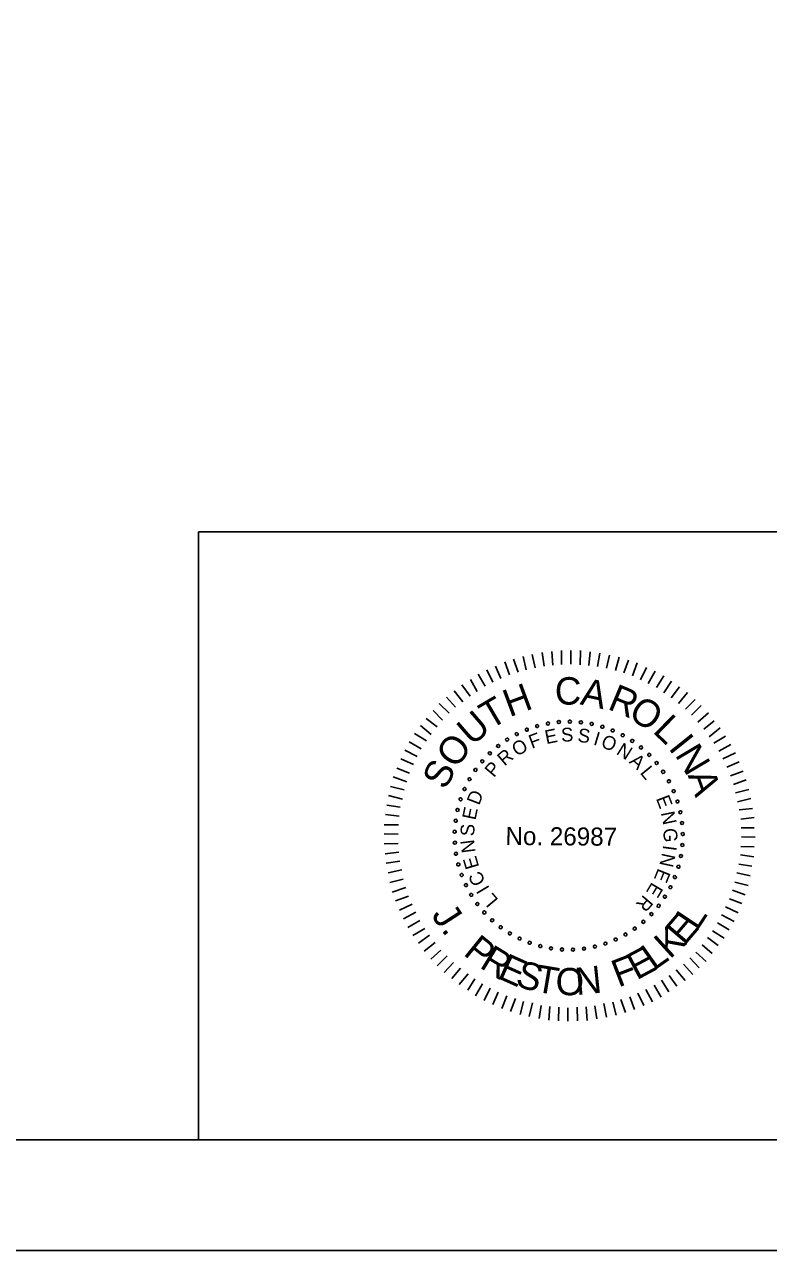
# Model space of a CAD drawing. Extents: x 96 to 240, y 601 to 689.
# Drawn here: x 183.23 to 196.68, y 601 to 623.18 of the extents above; entities that cross this region are included whole.
import ezdxf

# ---------------------------------------------------------------- set-up
doc = ezdxf.new("R2010")
doc.units = 0
for name, color, linetype in [('BR_BORDER LINES', 7, 'Continuous'), ('BR_TEXT', 7, 'Continuous'), ('Level 31', 7, 'Continuous')]:
    doc.layers.add(name, color=color, linetype=linetype)

msp = doc.modelspace()

# ---------------------------------------------------------------- linework, layer by layer
at = {"layer": 'BR_BORDER LINES'}
for p, q in [((186.375, 614.004), (207.836, 614.004)), ((186.375, 603.004), (186.375, 614.004)), ((103.173, 603.003), (237.837, 603.003))]:
    msp.add_line(p, q, dxfattribs=at)
at = {"layer": 'BR_TEXT'}
for p, q in [((192.938, 611.601), (192.94, 611.858)), ((193.106, 611.61), (193.108, 611.857)), ((193.274, 611.598), (193.283, 611.856)), ((191.996, 611.416), (191.912, 611.651)), ((192.154, 611.467), (192.067, 611.697)), ((192.299, 611.507), (192.246, 611.751)), ((192.464, 611.546), (192.407, 611.784)), ((192.622, 611.576), (192.586, 611.82)), ((192.78, 611.592), (192.765, 611.836)), ((193.435, 611.587), (193.455, 611.83)), ((193.59, 611.568), (193.633, 611.811)), ((193.751, 611.536), (193.808, 611.772)), ((193.915, 611.493), (193.979, 611.736)), ((194.063, 611.451), (194.15, 611.68)), ((194.22, 611.398), (194.308, 611.631)), ((191.555, 611.211), (191.433, 611.428)), ((191.693, 611.282), (191.588, 611.506)), ((191.841, 611.349), (191.747, 611.573)), ((194.364, 611.328), (194.475, 611.55)), ((194.507, 611.258), (194.633, 611.481)), ((194.658, 611.185), (194.787, 611.4)), ((191.289, 611.031), (191.133, 611.235)), ((191.413, 611.116), (191.292, 611.333)), ((194.791, 611.088), (194.927, 611.303)), ((194.924, 611.001), (195.07, 611.202)), ((191.023, 610.831), (190.856, 611.01)), ((191.154, 610.929), (190.995, 611.13)), ((195.054, 610.897), (195.216, 611.095)), ((195.18, 610.796), (195.353, 610.973)), ((190.788, 610.599), (190.614, 610.769)), ((190.905, 610.722), (190.728, 610.898)), ((195.292, 610.686), (195.465, 610.859)), ((190.687, 610.473), (190.489, 610.629)), ((195.404, 610.561), (195.595, 610.728)), ((195.513, 610.433), (195.7, 610.586)), ((190.496, 610.224), (190.281, 610.356)), ((190.583, 610.34), (190.385, 610.5)), ((195.608, 610.298), (195.805, 610.455)), ((195.696, 610.181), (195.907, 610.31)), ((190.399, 610.077), (190.184, 610.206)), ((195.784, 610.033), (195.998, 610.158)), ((190.259, 609.793), (190.03, 609.895)), ((190.329, 609.94), (190.103, 610.052)), ((195.855, 609.895), (196.086, 610.003)), ((190.189, 609.639), (189.957, 609.727)), ((195.926, 609.747), (196.154, 609.844)), ((195.994, 609.592), (196.221, 609.675)), ((190.14, 609.479), (189.894, 609.57)), ((196.047, 609.43), (196.278, 609.517)), ((190.062, 609.167), (189.812, 609.231)), ((190.091, 609.335), (189.847, 609.395)), ((196.087, 609.285), (196.328, 609.342)), ((190.019, 609.023), (189.776, 609.056)), ((196.12, 609.117), (196.361, 609.177)), ((196.153, 608.972), (196.39, 609.001)), ((190.001, 608.858), (189.754, 608.888)), ((196.179, 608.807), (196.423, 608.833)), ((189.981, 608.536), (189.73, 608.538)), ((189.989, 608.701), (189.732, 608.703)), ((196.185, 608.649), (196.425, 608.647)), ((189.986, 608.364), (189.729, 608.359)), ((196.182, 608.313), (196.422, 608.304)), ((196.194, 608.485), (196.438, 608.483)), ((189.996, 608.21), (189.748, 608.181)), ((196.174, 608.159), (196.418, 608.126)), ((190.011, 608.045), (189.767, 608.009)), ((190.051, 607.887), (189.8, 607.834)), ((196.145, 607.994), (196.382, 607.954)), ((190.077, 607.718), (189.833, 607.662)), ((196.074, 607.669), (196.314, 607.608)), ((196.11, 607.837), (196.349, 607.78)), ((190.124, 607.57), (189.876, 607.486)), ((190.171, 607.415), (189.937, 607.331)), ((196.031, 607.521), (196.261, 607.434)), ((190.238, 607.267), (190.007, 607.159)), ((195.905, 607.22), (196.131, 607.109)), ((195.975, 607.367), (196.201, 607.28)), ((190.306, 607.122), (190.078, 607.004)), ((190.373, 606.974), (190.156, 606.849)), ((195.832, 607.077), (196.061, 606.955)), ((190.468, 606.826), (190.251, 606.701)), ((195.668, 606.783), (195.877, 606.654)), ((195.759, 606.93), (195.971, 606.801)), ((190.553, 606.708), (190.353, 606.562)), ((190.655, 606.574), (190.454, 606.417)), ((195.481, 606.534), (195.665, 606.374)), ((195.578, 606.667), (195.773, 606.518)), ((190.753, 606.439), (190.577, 606.276)), ((190.869, 606.335), (190.689, 606.155)), ((195.256, 606.299), (195.426, 606.115)), ((195.37, 606.401), (195.557, 606.234)), ((190.985, 606.214), (190.815, 606.03)), ((191.114, 606.11), (190.952, 605.922)), ((195.014, 606.078), (195.173, 605.888)), ((195.142, 606.18), (195.312, 605.993)), ((191.248, 606.006), (191.088, 605.815)), ((191.37, 605.919), (191.245, 605.711)), ((194.748, 605.891), (194.88, 605.681)), ((194.883, 605.976), (195.025, 605.782)), ((191.51, 605.829), (191.385, 605.613)), ((191.647, 605.749), (191.539, 605.526)), ((191.794, 605.679), (191.696, 605.456)), ((194.317, 605.658), (194.425, 605.434)), ((194.462, 605.725), (194.583, 605.501)), ((194.613, 605.803), (194.739, 605.586)), ((191.948, 605.609), (191.86, 605.383)), ((192.105, 605.559), (192.014, 605.327)), ((192.249, 605.51), (192.192, 605.274)), ((192.414, 605.481), (192.353, 605.235)), ((192.571, 605.435), (192.532, 605.202)), ((192.729, 605.417), (192.71, 605.17)), ((193.384, 605.412), (193.4, 605.164)), ((193.539, 605.427), (193.578, 605.194)), ((193.701, 605.471), (193.754, 605.223)), ((193.866, 605.497), (193.926, 605.259)), ((194.014, 605.544), (194.098, 605.309)), ((194.172, 605.59), (194.256, 605.363)), ((192.887, 605.405), (192.885, 605.158)), ((193.055, 605.394), (193.053, 605.15)), ((193.223, 605.403), (193.228, 605.155))]:
    msp.add_line(p, q, dxfattribs=at)
for centre, start, end in [((192.498, 610.49), 16.1422, 196.1422), ((192.692, 610.536), 10.6038, 190.6038), ((192.692, 610.536), 190.6038, 10.6038), ((192.89, 610.563), 5.0653, 185.0653), ((192.89, 610.563), 185.0653, 5.0653), ((193.089, 610.57), 359.5268, 179.5268), ((193.089, 610.57), 179.5268, 359.5268), ((193.288, 610.558), 353.9884, 173.9884), ((193.288, 610.558), 173.9884, 353.9884), ((193.485, 610.528), 348.4499, 168.4499), ((193.485, 610.528), 168.4499, 348.4499), ((192.128, 610.344), 27.2191, 207.2191), ((192.128, 610.344), 207.2191, 27.2191), ((192.31, 610.426), 21.6807, 201.6807), ((192.31, 610.426), 201.6807, 21.6807), ((192.498, 610.49), 196.1422, 16.1422), ((193.678, 610.478), 162.9114, 342.9114), ((193.678, 610.478), 342.9114, 162.9114), ((193.865, 610.41), 157.373, 337.373), ((193.865, 610.41), 337.373, 157.373), ((194.045, 610.324), 151.8345, 331.8345), ((194.045, 610.324), 331.8345, 151.8345), ((191.793, 610.129), 38.2961, 218.2961), ((191.793, 610.129), 218.2961, 38.2961), ((191.955, 610.244), 32.7576, 212.7576), ((191.955, 610.244), 212.7576, 32.7576), ((194.216, 610.221), 146.2961, 326.2961), ((194.216, 610.221), 326.2961, 146.2961), ((194.376, 610.102), 140.7576, 320.7576), ((194.376, 610.102), 320.7576, 140.7576), ((191.505, 609.854), 49.373, 229.373), ((191.505, 609.854), 229.373, 49.373), ((191.642, 609.998), 43.8345, 223.8345), ((191.642, 609.998), 223.8345, 43.8345), ((194.524, 609.969), 135.2191, 315.2191), ((194.524, 609.969), 315.2191, 135.2191), ((194.658, 609.821), 309.6807, 129.6807), ((191.382, 609.697), 54.9114, 234.9114), ((191.382, 609.697), 234.9114, 54.9114), ((194.658, 609.821), 129.6807, 309.6807), ((194.777, 609.662), 124.1422, 304.1422), ((194.777, 609.662), 304.1422, 124.1422), ((191.275, 609.528), 60.4499, 240.4499), ((191.275, 609.528), 240.4499, 60.4499), ((194.881, 609.491), 118.6038, 298.6038), ((194.881, 609.491), 298.6038, 118.6038), ((191.113, 609.165), 71.5268, 251.5268), ((191.113, 609.165), 251.5268, 71.5268), ((191.185, 609.351), 65.9884, 245.9884), ((191.185, 609.351), 245.9884, 65.9884), ((194.967, 609.312), 113.0653, 293.0653), ((194.967, 609.312), 293.0653, 113.0653), ((191.058, 608.973), 77.0653, 257.0653), ((191.058, 608.973), 257.0653, 77.0653), ((195.036, 609.125), 107.5268, 287.5268), ((195.036, 609.125), 287.5268, 107.5268), ((195.087, 608.932), 101.9884, 281.9884), ((195.087, 608.932), 281.9884, 101.9884), ((191.023, 608.777), 82.6038, 262.6038), ((191.023, 608.777), 262.6038, 82.6038), ((195.118, 608.735), 96.4499, 276.4499), ((195.118, 608.735), 276.4499, 96.4499), ((191.006, 608.578), 88.1422, 268.1422), ((191.006, 608.578), 268.1422, 88.1422), ((195.131, 608.536), 90.9114, 270.9114), ((195.131, 608.536), 270.9114, 90.9114), ((191.009, 608.379), 93.6807, 273.6807), ((191.009, 608.379), 273.6807, 93.6807), ((195.124, 608.337), 85.373, 265.373), ((195.124, 608.337), 265.373, 85.373), ((191.031, 608.181), 99.2191, 279.2191), ((191.031, 608.181), 279.2191, 99.2191), ((195.098, 608.139), 79.8345, 259.8345), ((195.098, 608.139), 259.8345, 79.8345), ((191.072, 607.986), 104.7576, 284.7576), ((191.072, 607.986), 284.7576, 104.7576), ((195.053, 607.945), 74.2961, 254.2961), ((195.053, 607.945), 254.2961, 74.2961), ((191.132, 607.796), 110.2961, 290.2961), ((191.132, 607.796), 290.2961, 110.2961), ((191.209, 607.612), 115.8345, 295.8345), ((191.209, 607.612), 295.8345, 115.8345), ((194.989, 607.756), 68.7576, 248.7576), ((194.989, 607.756), 248.7576, 68.7576), ((191.305, 607.437), 121.373, 301.373), ((191.305, 607.437), 301.373, 121.373), ((194.809, 607.401), 57.6807, 237.6807), ((194.809, 607.401), 237.6807, 57.6807), ((194.908, 607.574), 63.2191, 243.2191), ((194.908, 607.574), 243.2191, 63.2191), ((191.416, 607.272), 126.9114, 306.9114), ((191.416, 607.272), 306.9114, 126.9114), ((194.694, 607.238), 52.1422, 232.1422), ((194.694, 607.238), 232.1422, 52.1422), ((191.543, 607.118), 132.4499, 312.4499), ((191.543, 607.118), 312.4499, 132.4499), ((191.684, 606.977), 137.9884, 317.9884), ((191.684, 606.977), 317.9884, 137.9884), ((194.42, 606.949), 41.0653, 221.0653), ((194.42, 606.949), 221.0653, 41.0653), ((194.564, 607.087), 46.6038, 226.6038), ((194.564, 607.087), 226.6038, 46.6038), ((191.838, 606.851), 143.5268, 323.5268), ((191.838, 606.851), 323.5268, 143.5268), ((192.004, 606.74), 149.0653, 329.0653), ((192.004, 606.74), 329.0653, 149.0653), ((194.095, 606.719), 29.9884, 209.9884), ((194.263, 606.826), 35.5268, 215.5268), ((194.263, 606.826), 215.5268, 35.5268), ((192.18, 606.646), 154.6038, 334.6038), ((192.18, 606.646), 334.6038, 154.6038), ((192.363, 606.569), 160.1422, 340.1422), ((192.363, 606.569), 340.1422, 160.1422), ((192.554, 606.51), 345.6807, 165.6807), ((193.541, 606.5), 13.373, 193.373), ((193.733, 606.555), 18.9114, 198.9114), ((193.733, 606.555), 198.9114, 18.9114), ((193.918, 606.628), 24.4499, 204.4499), ((193.918, 606.628), 204.4499, 24.4499), ((194.095, 606.719), 209.9884, 29.9884), ((192.554, 606.51), 165.6807, 345.6807), ((192.749, 606.469), 351.2191, 171.2191), ((192.749, 606.469), 171.2191, 351.2191), ((192.947, 606.448), 356.7576, 176.7576), ((192.947, 606.448), 176.7576, 356.7576), ((193.146, 606.446), 2.2961, 182.2961), ((193.146, 606.446), 182.2961, 2.2961), ((193.345, 606.463), 7.8345, 187.8345), ((193.345, 606.463), 187.8345, 7.8345), ((193.541, 606.5), 193.373, 13.373)]:
    msp.add_arc(centre, 0.028, start, end, dxfattribs=at)
at = {"layer": 'Level 31'}
msp.add_lwpolyline([(95.84, 689.004), (95.84, 601.004), (239.84, 601.004), (239.84, 689.004)], dxfattribs=at)

# ---------------------------------------------------------------- texts
at = {"layer": 'BR_TEXT'}
for s, height, rotation, p in [('H', 0.496, 20.3637, (191.997, 610.647)), ('C', 0.496, 359.5482, (192.815, 610.88)), ('A', 0.496, 348.1981, (193.261, 610.884)), ('R', 0.496, 337.4344, (193.754, 610.804)), ('T', 0.496, 30.4992, (191.646, 610.417)), ('O', 0.496, 326.5869, (194.123, 610.657)), ('U', 0.496, 40.8022, (191.321, 610.118)), ('L', 0.496, 315.9488, (194.573, 610.386)), ('O', 0.496, 52.0267, (191.023, 609.702)), ('F', 0.249, 20.6127, (192.402, 610.076)), ('E', 0.249, 11.4103, (192.663, 610.162)), ('S', 0.249, 2.208, (192.934, 610.206)), ('S', 0.249, 352.6608, (193.22, 610.206)), ('I', 0.249, 343.1136, (193.5, 610.157)), ('O', 0.249, 338.4392, (193.634, 610.117)), ('I', 0.496, 308.6613, (194.859, 610.089)), ('O', 0.249, 30.8477, (192.133, 609.932)), ('N', 0.249, 328.2042, (193.913, 609.991)), ('N', 0.496, 300.7037, (194.981, 609.971)), ('S', 0.496, 63.2511, (190.842, 609.32)), ('R', 0.249, 40.3949, (191.908, 609.756)), ('A', 0.249, 318.657, (194.149, 609.831)), ('P', 0.249, 49.9421, (191.716, 609.546)), ('L', 0.249, 309.4546, (194.348, 609.642)), ('A', 0.496, 289.4792, (195.218, 609.599)), ('D', 0.249, 69.0364, (191.448, 609.045)), ('E', 0.249, 291.049, (194.643, 609.181)), ('E', 0.249, 78.2388, (191.382, 608.778)), ('N', 0.249, 281.8466, (194.732, 608.921)), ('S', 0.249, 87.786, (191.359, 608.494)), ('No. 26987', 0.327, 359.5268, (191.924, 608.34)), ('G', 0.249, 272.2995, (194.779, 608.639)), ('N', 0.249, 97.3332, (191.384, 608.21)), ('I', 0.249, 262.4084, (194.778, 608.344)), ('E', 0.249, 106.5355, (191.452, 607.944)), ('N', 0.249, 257.7339, (194.759, 608.206)), ('C', 0.249, 116.4266, (191.571, 607.674)), ('E', 0.249, 248.1867, (194.687, 607.93)), ('E', 0.249, 238.9844, (194.575, 607.679)), ('I', 0.249, 121.1011, (191.644, 607.554)), ('L', 0.249, 129.9595, (191.806, 607.345)), ('R', 0.249, 229.782, (194.425, 607.449)), ('J', 0.494, 302.9559, (190.575, 607.071)), ('E', 0.494, 49.3639, (195.159, 606.504)), ('L', 0.494, 56.4247, (195.389, 606.775)), ('.', 0.494, 309.3974, (190.751, 606.8)), ('K', 0.494, 42.3031, (194.897, 606.263)), ('P', 0.494, 321.1035, (191.145, 606.363)), ('R', 0.494, 328.5359, (191.438, 606.13)), ('L', 0.494, 35.2422, (194.608, 606.057)), ('E', 0.494, 335.9684, (191.758, 605.938)), ('F', 0.494, 21.1206, (193.966, 605.758)), ('E', 0.494, 28.1814, (194.296, 605.887)), ('S', 0.494, 343.0292, (192.084, 605.795)), ('T', 0.494, 350.4617, (192.442, 605.689)), ('O', 0.494, 358.1419, (192.824, 605.629)), ('N', 0.494, 5.8221, (193.21, 605.621))]:
    msp.add_text(s, height=height, rotation=rotation, dxfattribs=at).set_placement(p)

doc.saveas('drawing.dxf')
